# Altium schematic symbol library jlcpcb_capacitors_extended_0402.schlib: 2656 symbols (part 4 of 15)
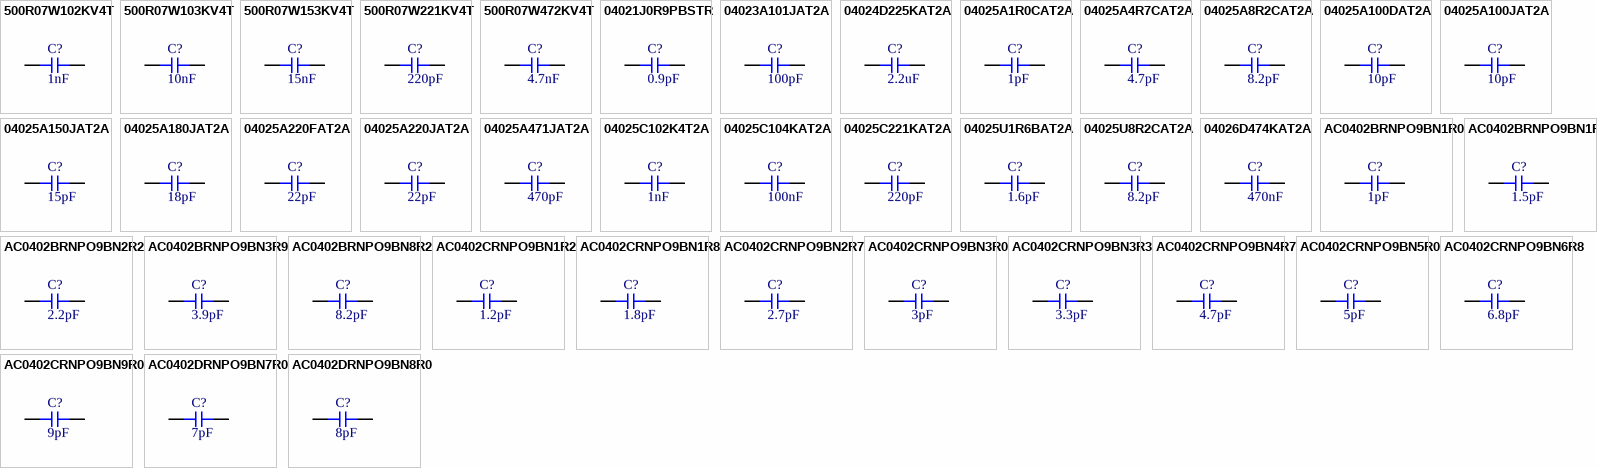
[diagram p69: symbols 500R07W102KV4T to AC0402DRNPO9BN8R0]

## 04026D474KAT2A
designator C?  Capacitance: 470nF  (hidden comment: *)
Capacitor, Ceramic (MLCC), 470nF, ±10%, 6.3V, X5R, ±10%, SMD 0402; Manufacturer: AVX; Manufacturer Part Number: 04026D474KAT2A
footprint CAP-0402 (0402 (1005M) Capacitor)
pins: 1, 2

## AC0402BRNPO9BN1R0
designator C?  Capacitance: 1pF  (hidden comment: *)
Capacitor, Ceramic (MLCC), 1pF, ±0.1pF, 50V, NP0, ±0.1pF, SMD 0402; Manufacturer: YAGEO; Manufacturer Part Number: AC0402BRNPO9BN1R0
footprint CAP-0402 (0402 (1005M) Capacitor)
pins: 1, 2

## AC0402BRNPO9BN1R5
designator C?  Capacitance: 1.5pF  (hidden comment: *)
Capacitor, Ceramic (MLCC), 1.5pF, ±0.1pF, 50V, NP0, ±0.1pF, SMD 0402; Manufacturer: YAGEO; Manufacturer Part Number: AC0402BRNPO9BN1R5
footprint CAP-0402 (0402 (1005M) Capacitor)
pins: 1, 2

## AC0402BRNPO9BN2R2
designator C?  Capacitance: 2.2pF  (hidden comment: *)
Capacitor, Ceramic (MLCC), 2.2pF, ±0.1pF, 50V, NP0, ±0.1pF, SMD 0402; Manufacturer: YAGEO; Manufacturer Part Number: AC0402BRNPO9BN2R2
footprint CAP-0402 (0402 (1005M) Capacitor)
pins: 1, 2

## AC0402BRNPO9BN3R9
designator C?  Capacitance: 3.9pF  (hidden comment: *)
Capacitor, Ceramic (MLCC), 3.9pF, ±0.1pF, 50V, NP0, ±0.1pF, SMD 0402; Manufacturer: YAGEO; Manufacturer Part Number: AC0402BRNPO9BN3R9
footprint CAP-0402 (0402 (1005M) Capacitor)
pins: 1, 2

## AC0402BRNPO9BN8R2
designator C?  Capacitance: 8.2pF  (hidden comment: *)
Capacitor, Ceramic (MLCC), 8.2pF, ±0.1pF, 50V, NP0, ±0.1pF, SMD 0402; Manufacturer: YAGEO; Manufacturer Part Number: AC0402BRNPO9BN8R2
footprint CAP-0402 (0402 (1005M) Capacitor)
pins: 1, 2

## AC0402CRNPO9BN1R2
designator C?  Capacitance: 1.2pF  (hidden comment: *)
Capacitor, Ceramic (MLCC), 1.2pF, ±0.25pF, 50V, NP0, ±0.25pF, SMD 0402; Manufacturer: YAGEO; Manufacturer Part Number: AC0402CRNPO9BN1R2
footprint CAP-0402 (0402 (1005M) Capacitor)
pins: 1, 2

## AC0402CRNPO9BN1R8
designator C?  Capacitance: 1.8pF  (hidden comment: *)
Capacitor, Ceramic (MLCC), 1.8pF, ±0.25pF, 50V, NP0, ±0.25pF, SMD 0402; Manufacturer: YAGEO; Manufacturer Part Number: AC0402CRNPO9BN1R8
footprint CAP-0402 (0402 (1005M) Capacitor)
pins: 1, 2

## AC0402CRNPO9BN2R7
designator C?  Capacitance: 2.7pF  (hidden comment: *)
Capacitor, Ceramic (MLCC), 2.7pF, ±0.25pF, 50V, NP0, ±0.25pF, SMD 0402; Manufacturer: YAGEO; Manufacturer Part Number: AC0402CRNPO9BN2R7
footprint CAP-0402 (0402 (1005M) Capacitor)
pins: 1, 2

## AC0402CRNPO9BN3R0
designator C?  Capacitance: 3pF  (hidden comment: *)
Capacitor, Ceramic (MLCC), 3pF, ±0.25pF, 50V, NP0, ±0.25pF, SMD 0402; Manufacturer: YAGEO; Manufacturer Part Number: AC0402CRNPO9BN3R0
footprint CAP-0402 (0402 (1005M) Capacitor)
pins: 1, 2

## AC0402CRNPO9BN3R3
designator C?  Capacitance: 3.3pF  (hidden comment: *)
Capacitor, Ceramic (MLCC), 3.3pF, ±0.25pF, 50V, NP0, ±0.25pF, SMD 0402; Manufacturer: YAGEO; Manufacturer Part Number: AC0402CRNPO9BN3R3
footprint CAP-0402 (0402 (1005M) Capacitor)
pins: 1, 2

## AC0402CRNPO9BN4R7
designator C?  Capacitance: 4.7pF  (hidden comment: *)
Capacitor, Ceramic (MLCC), 4.7pF, ±0.25pF, 50V, NP0, ±0.25pF, SMD 0402; Manufacturer: YAGEO; Manufacturer Part Number: AC0402CRNPO9BN4R7
footprint CAP-0402 (0402 (1005M) Capacitor)
pins: 1, 2

## AC0402CRNPO9BN5R0
designator C?  Capacitance: 5pF  (hidden comment: *)
Capacitor, Ceramic (MLCC), 5pF, ±0.25pF, 50V, NP0, ±0.25pF, SMD 0402; Manufacturer: YAGEO; Manufacturer Part Number: AC0402CRNPO9BN5R0
footprint CAP-0402 (0402 (1005M) Capacitor)
pins: 1, 2

## AC0402CRNPO9BN6R8
designator C?  Capacitance: 6.8pF  (hidden comment: *)
Capacitor, Ceramic (MLCC), 6.8pF, ±0.25pF, 50V, NP0, ±0.25pF, SMD 0402; Manufacturer: YAGEO; Manufacturer Part Number: AC0402CRNPO9BN6R8
footprint CAP-0402 (0402 (1005M) Capacitor)
pins: 1, 2

## AC0402CRNPO9BN9R0
designator C?  Capacitance: 9pF  (hidden comment: *)
Capacitor, Ceramic (MLCC), 9pF, ±0.25pF, 50V, NP0, ±0.25pF, SMD 0402; Manufacturer: YAGEO; Manufacturer Part Number: AC0402CRNPO9BN9R0
footprint CAP-0402 (0402 (1005M) Capacitor)
pins: 1, 2

## AC0402DRNPO9BN7R0
designator C?  Capacitance: 7pF  (hidden comment: *)
Capacitor, Ceramic (MLCC), 7pF, ±0.5pF, 50V, NP0, ±0.5pF, SMD 0402; Manufacturer: YAGEO; Manufacturer Part Number: AC0402DRNPO9BN7R0
footprint CAP-0402 (0402 (1005M) Capacitor)
pins: 1, 2

## AC0402DRNPO9BN8R0
designator C?  Capacitance: 8pF  (hidden comment: *)
Capacitor, Ceramic (MLCC), 8pF, ±0.5pF, 50V, NP0, ±0.5pF, SMD 0402; Manufacturer: YAGEO; Manufacturer Part Number: AC0402DRNPO9BN8R0
footprint CAP-0402 (0402 (1005M) Capacitor)
pins: 1, 2

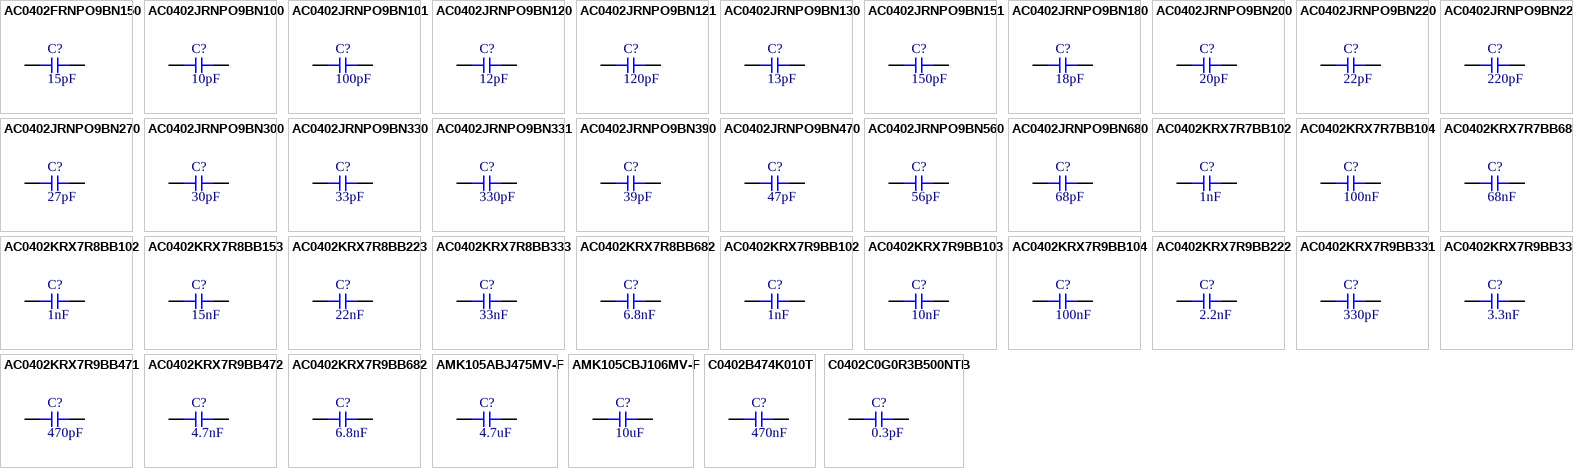
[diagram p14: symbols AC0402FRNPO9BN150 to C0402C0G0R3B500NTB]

## AC0402FRNPO9BN150
designator C?  Capacitance: 15pF  (hidden comment: *)
Capacitor, Ceramic (MLCC), 15pF, ±1%, 50V, NP0, ±1%, SMD 0402; Manufacturer: YAGEO; Manufacturer Part Number: AC0402FRNPO9BN150
footprint CAP-0402 (0402 (1005M) Capacitor)
pins: 1, 2

## AC0402JRNPO9BN100
designator C?  Capacitance: 10pF  (hidden comment: *)
Capacitor, Ceramic (MLCC), 10pF, ±5%, 50V, NP0, ±5%, SMD 0402; Manufacturer: YAGEO; Manufacturer Part Number: AC0402JRNPO9BN100
footprint CAP-0402 (0402 (1005M) Capacitor)
pins: 1, 2

## AC0402JRNPO9BN101
designator C?  Capacitance: 100pF  (hidden comment: *)
Capacitor, Ceramic (MLCC), 100pF, ±5%, 50V, NP0, ±5%, SMD 0402; Manufacturer: YAGEO; Manufacturer Part Number: AC0402JRNPO9BN101
footprint CAP-0402 (0402 (1005M) Capacitor)
pins: 1, 2

## AC0402JRNPO9BN120
designator C?  Capacitance: 12pF  (hidden comment: *)
Capacitor, Ceramic (MLCC), 12pF, ±5%, 50V, NP0, ±5%, SMD 0402; Manufacturer: YAGEO; Manufacturer Part Number: AC0402JRNPO9BN120
footprint CAP-0402 (0402 (1005M) Capacitor)
pins: 1, 2

## AC0402JRNPO9BN121
designator C?  Capacitance: 120pF  (hidden comment: *)
Capacitor, Ceramic (MLCC), 120pF, ±5%, 50V, NP0, ±5%, SMD 0402; Manufacturer: YAGEO; Manufacturer Part Number: AC0402JRNPO9BN121
footprint CAP-0402 (0402 (1005M) Capacitor)
pins: 1, 2

## AC0402JRNPO9BN130
designator C?  Capacitance: 13pF  (hidden comment: *)
Capacitor, Ceramic (MLCC), 13pF, ±5%, 50V, NP0, ±5%, SMD 0402; Manufacturer: YAGEO; Manufacturer Part Number: AC0402JRNPO9BN130
footprint CAP-0402 (0402 (1005M) Capacitor)
pins: 1, 2

## AC0402JRNPO9BN151
designator C?  Capacitance: 150pF  (hidden comment: *)
Capacitor, Ceramic (MLCC), 150pF, ±5%, 50V, NP0, ±5%, SMD 0402; Manufacturer: YAGEO; Manufacturer Part Number: AC0402JRNPO9BN151
footprint CAP-0402 (0402 (1005M) Capacitor)
pins: 1, 2

## AC0402JRNPO9BN180
designator C?  Capacitance: 18pF  (hidden comment: *)
Capacitor, Ceramic (MLCC), 18pF, ±5%, 50V, NP0, ±5%, SMD 0402; Manufacturer: YAGEO; Manufacturer Part Number: AC0402JRNPO9BN180
footprint CAP-0402 (0402 (1005M) Capacitor)
pins: 1, 2

## AC0402JRNPO9BN200
designator C?  Capacitance: 20pF  (hidden comment: *)
Capacitor, Ceramic (MLCC), 20pF, ±5%, 50V, NP0, ±5%, SMD 0402; Manufacturer: YAGEO; Manufacturer Part Number: AC0402JRNPO9BN200
footprint CAP-0402 (0402 (1005M) Capacitor)
pins: 1, 2

## AC0402JRNPO9BN220
designator C?  Capacitance: 22pF  (hidden comment: *)
Capacitor, Ceramic (MLCC), 22pF, ±5%, 50V, NP0, ±5%, SMD 0402; Manufacturer: YAGEO; Manufacturer Part Number: AC0402JRNPO9BN220
footprint CAP-0402 (0402 (1005M) Capacitor)
pins: 1, 2

## AC0402JRNPO9BN221
designator C?  Capacitance: 220pF  (hidden comment: *)
Capacitor, Ceramic (MLCC), 220pF, ±5%, 50V, NP0, ±5%, SMD 0402; Manufacturer: YAGEO; Manufacturer Part Number: AC0402JRNPO9BN221
footprint CAP-0402 (0402 (1005M) Capacitor)
pins: 1, 2

## AC0402JRNPO9BN270
designator C?  Capacitance: 27pF  (hidden comment: *)
Capacitor, Ceramic (MLCC), 27pF, ±5%, 50V, NP0, ±5%, SMD 0402; Manufacturer: YAGEO; Manufacturer Part Number: AC0402JRNPO9BN270
footprint CAP-0402 (0402 (1005M) Capacitor)
pins: 1, 2

## AC0402JRNPO9BN300
designator C?  Capacitance: 30pF  (hidden comment: *)
Capacitor, Ceramic (MLCC), 30pF, ±5%, 50V, NP0, ±5%, SMD 0402; Manufacturer: YAGEO; Manufacturer Part Number: AC0402JRNPO9BN300
footprint CAP-0402 (0402 (1005M) Capacitor)
pins: 1, 2

## AC0402JRNPO9BN330
designator C?  Capacitance: 33pF  (hidden comment: *)
Capacitor, Ceramic (MLCC), 33pF, ±5%, 50V, NP0, ±5%, SMD 0402; Manufacturer: YAGEO; Manufacturer Part Number: AC0402JRNPO9BN330
footprint CAP-0402 (0402 (1005M) Capacitor)
pins: 1, 2

## AC0402JRNPO9BN331
designator C?  Capacitance: 330pF  (hidden comment: *)
Capacitor, Ceramic (MLCC), 330pF, ±5%, 50V, NP0, ±5%, SMD 0402; Manufacturer: YAGEO; Manufacturer Part Number: AC0402JRNPO9BN331
footprint CAP-0402 (0402 (1005M) Capacitor)
pins: 1, 2

## AC0402JRNPO9BN390
designator C?  Capacitance: 39pF  (hidden comment: *)
Capacitor, Ceramic (MLCC), 39pF, ±5%, 50V, NP0, ±5%, SMD 0402; Manufacturer: YAGEO; Manufacturer Part Number: AC0402JRNPO9BN390
footprint CAP-0402 (0402 (1005M) Capacitor)
pins: 1, 2

## AC0402JRNPO9BN470
designator C?  Capacitance: 47pF  (hidden comment: *)
Capacitor, Ceramic (MLCC), 47pF, ±5%, 50V, NP0, ±5%, SMD 0402; Manufacturer: YAGEO; Manufacturer Part Number: AC0402JRNPO9BN470
footprint CAP-0402 (0402 (1005M) Capacitor)
pins: 1, 2

## AC0402JRNPO9BN560
designator C?  Capacitance: 56pF  (hidden comment: *)
Capacitor, Ceramic (MLCC), 56pF, ±5%, 50V, NP0, ±5%, SMD 0402; Manufacturer: YAGEO; Manufacturer Part Number: AC0402JRNPO9BN560
footprint CAP-0402 (0402 (1005M) Capacitor)
pins: 1, 2

## AC0402JRNPO9BN680
designator C?  Capacitance: 68pF  (hidden comment: *)
Capacitor, Ceramic (MLCC), 68pF, ±5%, 50V, NP0, ±5%, SMD 0402; Manufacturer: YAGEO; Manufacturer Part Number: AC0402JRNPO9BN680
footprint CAP-0402 (0402 (1005M) Capacitor)
pins: 1, 2

## AC0402KRX7R7BB102
designator C?  Capacitance: 1nF  (hidden comment: *)
Capacitor, Ceramic (MLCC), 1nF, ±10%, 16V, X7R, ±10%, SMD 0402; Manufacturer: YAGEO; Manufacturer Part Number: AC0402KRX7R7BB102
footprint CAP-0402 (0402 (1005M) Capacitor)
pins: 1, 2

## AC0402KRX7R7BB104
designator C?  Capacitance: 100nF  (hidden comment: *)
Capacitor, Ceramic (MLCC), 100nF, ±10%, 16V, X7R, ±10%, SMD 0402; Manufacturer: YAGEO; Manufacturer Part Number: AC0402KRX7R7BB104
footprint CAP-0402 (0402 (1005M) Capacitor)
pins: 1, 2

## AC0402KRX7R7BB683
designator C?  Capacitance: 68nF  (hidden comment: *)
Capacitor, Ceramic (MLCC), 68nF, ±10%, 16V, X7R, ±10%, SMD 0402; Manufacturer: YAGEO; Manufacturer Part Number: AC0402KRX7R7BB683
footprint CAP-0402 (0402 (1005M) Capacitor)
pins: 1, 2

## AC0402KRX7R8BB102
designator C?  Capacitance: 1nF  (hidden comment: *)
Capacitor, Ceramic (MLCC), 1nF, ±10%, 25V, X7R, ±10%, SMD 0402; Manufacturer: YAGEO; Manufacturer Part Number: AC0402KRX7R8BB102
footprint CAP-0402 (0402 (1005M) Capacitor)
pins: 1, 2

## AC0402KRX7R8BB153
designator C?  Capacitance: 15nF  (hidden comment: *)
Capacitor, Ceramic (MLCC), 15nF, ±10%, 25V, X7R, ±10%, SMD 0402; Manufacturer: YAGEO; Manufacturer Part Number: AC0402KRX7R8BB153
footprint CAP-0402 (0402 (1005M) Capacitor)
pins: 1, 2

## AC0402KRX7R8BB223
designator C?  Capacitance: 22nF  (hidden comment: *)
Capacitor, Ceramic (MLCC), 22nF, ±10%, 25V, X7R, ±10%, SMD 0402; Manufacturer: YAGEO; Manufacturer Part Number: AC0402KRX7R8BB223
footprint CAP-0402 (0402 (1005M) Capacitor)
pins: 1, 2

## AC0402KRX7R8BB333
designator C?  Capacitance: 33nF  (hidden comment: *)
Capacitor, Ceramic (MLCC), 33nF, ±10%, 25V, X7R, ±10%, SMD 0402; Manufacturer: YAGEO; Manufacturer Part Number: AC0402KRX7R8BB333
footprint CAP-0402 (0402 (1005M) Capacitor)
pins: 1, 2

## AC0402KRX7R8BB682
designator C?  Capacitance: 6.8nF  (hidden comment: *)
Capacitor, Ceramic (MLCC), 6.8nF, ±10%, 25V, X7R, ±10%, SMD 0402; Manufacturer: YAGEO; Manufacturer Part Number: AC0402KRX7R8BB682
footprint CAP-0402 (0402 (1005M) Capacitor)
pins: 1, 2

## AC0402KRX7R9BB102
designator C?  Capacitance: 1nF  (hidden comment: *)
Capacitor, Ceramic (MLCC), 1nF, ±10%, 50V, X7R, ±10%, SMD 0402; Manufacturer: YAGEO; Manufacturer Part Number: AC0402KRX7R9BB102
footprint CAP-0402 (0402 (1005M) Capacitor)
pins: 1, 2

## AC0402KRX7R9BB103
designator C?  Capacitance: 10nF  (hidden comment: *)
Capacitor, Ceramic (MLCC), 10nF, ±10%, 50V, X7R, ±10%, SMD 0402; Manufacturer: YAGEO; Manufacturer Part Number: AC0402KRX7R9BB103
footprint CAP-0402 (0402 (1005M) Capacitor)
pins: 1, 2

## AC0402KRX7R9BB104
designator C?  Capacitance: 100nF  (hidden comment: *)
Capacitor, Ceramic (MLCC), 100nF, ±10%, 50V, X7R, ±10%, SMD 0402; Manufacturer: YAGEO; Manufacturer Part Number: AC0402KRX7R9BB104
footprint CAP-0402 (0402 (1005M) Capacitor)
pins: 1, 2

## AC0402KRX7R9BB222
designator C?  Capacitance: 2.2nF  (hidden comment: *)
Capacitor, Ceramic (MLCC), 2.2nF, ±10%, 50V, X7R, ±10%, SMD 0402; Manufacturer: YAGEO; Manufacturer Part Number: AC0402KRX7R9BB222
footprint CAP-0402 (0402 (1005M) Capacitor)
pins: 1, 2

## AC0402KRX7R9BB331
designator C?  Capacitance: 330pF  (hidden comment: *)
Capacitor, Ceramic (MLCC), 330pF, ±10%, 50V, X7R, ±10%, SMD 0402; Manufacturer: YAGEO; Manufacturer Part Number: AC0402KRX7R9BB331
footprint CAP-0402 (0402 (1005M) Capacitor)
pins: 1, 2

## AC0402KRX7R9BB332
designator C?  Capacitance: 3.3nF  (hidden comment: *)
Capacitor, Ceramic (MLCC), 3.3nF, ±10%, 50V, X7R, ±10%, SMD 0402; Manufacturer: YAGEO; Manufacturer Part Number: AC0402KRX7R9BB332
footprint CAP-0402 (0402 (1005M) Capacitor)
pins: 1, 2

## AC0402KRX7R9BB471
designator C?  Capacitance: 470pF  (hidden comment: *)
Capacitor, Ceramic (MLCC), 470pF, ±10%, 50V, X7R, ±10%, SMD 0402; Manufacturer: YAGEO; Manufacturer Part Number: AC0402KRX7R9BB471
footprint CAP-0402 (0402 (1005M) Capacitor)
pins: 1, 2

## AC0402KRX7R9BB472
designator C?  Capacitance: 4.7nF  (hidden comment: *)
Capacitor, Ceramic (MLCC), 4.7nF, ±10%, 50V, X7R, ±10%, SMD 0402; Manufacturer: YAGEO; Manufacturer Part Number: AC0402KRX7R9BB472
footprint CAP-0402 (0402 (1005M) Capacitor)
pins: 1, 2

## AC0402KRX7R9BB682
designator C?  Capacitance: 6.8nF  (hidden comment: *)
Capacitor, Ceramic (MLCC), 6.8nF, ±10%, 50V, X7R, ±10%, SMD 0402; Manufacturer: YAGEO; Manufacturer Part Number: AC0402KRX7R9BB682
footprint CAP-0402 (0402 (1005M) Capacitor)
pins: 1, 2

## AMK105ABJ475MV-F
designator C?  Capacitance: 4.7uF  (hidden comment: *)
Capacitor, Ceramic (MLCC), 4.7uF, ±20%, 4V, X5R, ±20%, SMD 0402; Manufacturer: Taiyo Yuden; Manufacturer Part Number: AMK105ABJ475MV-F
footprint CAP-0402 (0402 (1005M) Capacitor)
pins: 1, 2

## AMK105CBJ106MV-F
designator C?  Capacitance: 10uF  (hidden comment: *)
Capacitor, Ceramic (MLCC), 10uF, ±20%, 4V, X5R, ±20%, SMD 0402; Manufacturer: Taiyo Yuden; Manufacturer Part Number: AMK105CBJ106MV-F
footprint CAP-0402 (0402 (1005M) Capacitor)
pins: 1, 2

## C0402B474K010T
designator C?  Capacitance: 470nF  (hidden comment: *)
Capacitor, Ceramic (MLCC), 470nF, ±10%, 10V, X5R, ±10%, SMD 0402; Manufacturer: IHHEC(HOLY STONE ENTERPRISE CO., LTD); Manufacturer Part Number: C0402B474K010T
footprint CAP-0402 (0402 (1005M) Capacitor)
pins: 1, 2

## C0402C0G0R3B500NTB
designator C?  Capacitance: 0.3pF  (hidden comment: *)
Capacitor, Ceramic (MLCC), 0.3pF, ±0.1pF, 50V, C0G, ±0.1pF, SMD 0402; Manufacturer: EYANG(Shenzhen Eyang Tech Development); Manufacturer Part Number: C0402C0G0R3B500NTB
footprint CAP-0402 (0402 (1005M) Capacitor)
pins: 1, 2

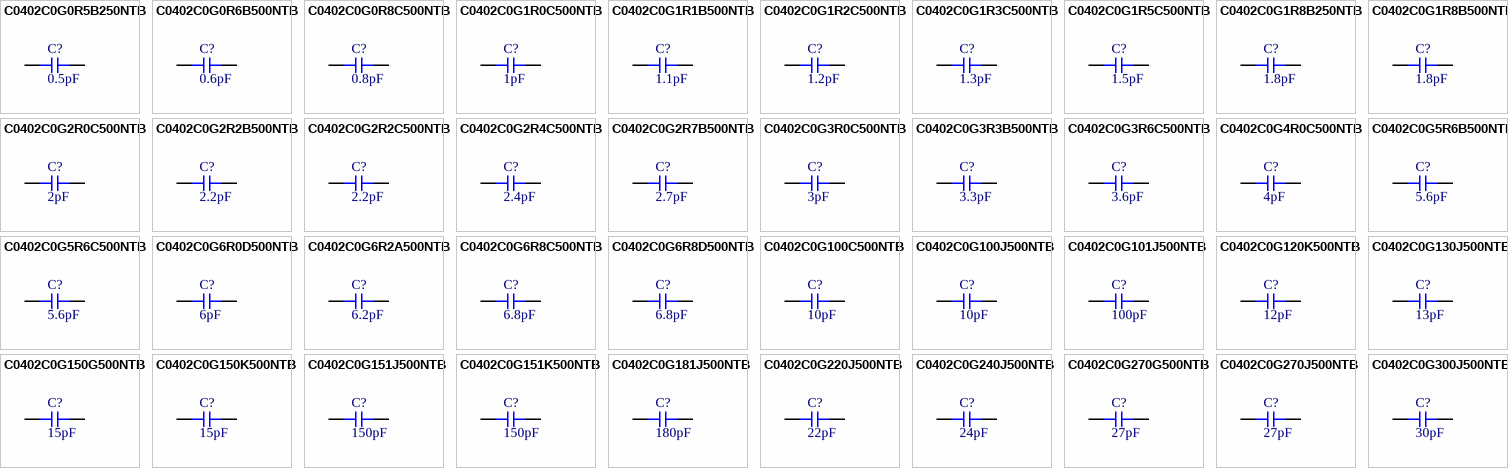
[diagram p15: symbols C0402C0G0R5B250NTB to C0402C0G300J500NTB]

## C0402C0G0R5B250NTB
designator C?  Capacitance: 0.5pF  (hidden comment: *)
Capacitor, Ceramic (MLCC), 0.5pF, ±0.1pF, 25V, C0G, ±0.1pF, SMD 0402; Manufacturer: EYANG(Shenzhen Eyang Tech Development); Manufacturer Part Number: C0402C0G0R5B250NTB
footprint CAP-0402 (0402 (1005M) Capacitor)
pins: 1, 2

## C0402C0G0R6B500NTB
designator C?  Capacitance: 0.6pF  (hidden comment: *)
Capacitor, Ceramic (MLCC), 0.6pF, ±0.1pF, 50V, C0G, ±0.1pF, SMD 0402; Manufacturer: EYANG(Shenzhen Eyang Tech Development); Manufacturer Part Number: C0402C0G0R6B500NTB
footprint CAP-0402 (0402 (1005M) Capacitor)
pins: 1, 2

## C0402C0G0R8C500NTB
designator C?  Capacitance: 0.8pF  (hidden comment: *)
Capacitor, Ceramic (MLCC), 0.8pF, ±0.25pF, 50V, C0G, ±0.25pF, SMD 0402; Manufacturer: EYANG(Shenzhen Eyang Tech Development); Manufacturer Part Number: C0402C0G0R8C500NTB
footprint CAP-0402 (0402 (1005M) Capacitor)
pins: 1, 2

## C0402C0G1R0C500NTB
designator C?  Capacitance: 1pF  (hidden comment: *)
Capacitor, Ceramic (MLCC), 1pF, ±0.25pF, 50V, C0G, ±0.25pF, SMD 0402; Manufacturer: EYANG(Shenzhen Eyang Tech Development); Manufacturer Part Number: C0402C0G1R0C500NTB
footprint CAP-0402 (0402 (1005M) Capacitor)
pins: 1, 2

## C0402C0G1R1B500NTB
designator C?  Capacitance: 1.1pF  (hidden comment: *)
Capacitor, Ceramic (MLCC), 1.1pF, ±0.1pF, 50V, C0G, ±0.1pF, SMD 0402; Manufacturer: EYANG(Shenzhen Eyang Tech Development); Manufacturer Part Number: C0402C0G1R1B500NTB
footprint CAP-0402 (0402 (1005M) Capacitor)
pins: 1, 2

## C0402C0G1R2C500NTB
designator C?  Capacitance: 1.2pF  (hidden comment: *)
Capacitor, Ceramic (MLCC), 1.2pF, ±0.25pF, 50V, C0G, ±0.25pF, SMD 0402; Manufacturer: EYANG(Shenzhen Eyang Tech Development); Manufacturer Part Number: C0402C0G1R2C500NTB
footprint CAP-0402 (0402 (1005M) Capacitor)
pins: 1, 2

## C0402C0G1R3C500NTB
designator C?  Capacitance: 1.3pF  (hidden comment: *)
Capacitor, Ceramic (MLCC), 1.3pF, ±0.25pF, 50V, C0G, ±0.25pF, SMD 0402; Manufacturer: EYANG(Shenzhen Eyang Tech Development); Manufacturer Part Number: C0402C0G1R3C500NTB
footprint CAP-0402 (0402 (1005M) Capacitor)
pins: 1, 2

## C0402C0G1R5C500NTB
designator C?  Capacitance: 1.5pF  (hidden comment: *)
Capacitor, Ceramic (MLCC), 1.5pF, ±0.25pF, 50V, C0G, ±0.25pF, SMD 0402; Manufacturer: EYANG(Shenzhen Eyang Tech Development); Manufacturer Part Number: C0402C0G1R5C500NTB
footprint CAP-0402 (0402 (1005M) Capacitor)
pins: 1, 2

## C0402C0G1R8B250NTB
designator C?  Capacitance: 1.8pF  (hidden comment: *)
Capacitor, Ceramic (MLCC), 1.8pF, ±0.1pF, 25V, C0G, ±0.1pF, SMD 0402; Manufacturer: EYANG(Shenzhen Eyang Tech Development); Manufacturer Part Number: C0402C0G1R8B250NTB
footprint CAP-0402 (0402 (1005M) Capacitor)
pins: 1, 2

## C0402C0G1R8B500NTB
designator C?  Capacitance: 1.8pF  (hidden comment: *)
Capacitor, Ceramic (MLCC), 1.8pF, ±0.1pF, 50V, C0G, ±0.1pF, SMD 0402; Manufacturer: EYANG(Shenzhen Eyang Tech Development); Manufacturer Part Number: C0402C0G1R8B500NTB
footprint CAP-0402 (0402 (1005M) Capacitor)
pins: 1, 2

## C0402C0G2R0C500NTB
designator C?  Capacitance: 2pF  (hidden comment: *)
Capacitor, Ceramic (MLCC), 2pF, ±0.25pF, 50V, C0G, ±0.25pF, SMD 0402; Manufacturer: EYANG(Shenzhen Eyang Tech Development); Manufacturer Part Number: C0402C0G2R0C500NTB
footprint CAP-0402 (0402 (1005M) Capacitor)
pins: 1, 2

## C0402C0G2R2B500NTB
designator C?  Capacitance: 2.2pF  (hidden comment: *)
Capacitor, Ceramic (MLCC), 2.2pF, ±0.1pF, 50V, C0G, ±0.1pF, SMD 0402; Manufacturer: EYANG(Shenzhen Eyang Tech Development); Manufacturer Part Number: C0402C0G2R2B500NTB
footprint CAP-0402 (0402 (1005M) Capacitor)
pins: 1, 2

## C0402C0G2R2C500NTB
designator C?  Capacitance: 2.2pF  (hidden comment: *)
Capacitor, Ceramic (MLCC), 2.2pF, ±0.25pF, 50V, C0G, ±0.25pF, SMD 0402; Manufacturer: EYANG(Shenzhen Eyang Tech Development); Manufacturer Part Number: C0402C0G2R2C500NTB
footprint CAP-0402 (0402 (1005M) Capacitor)
pins: 1, 2

## C0402C0G2R4C500NTB
designator C?  Capacitance: 2.4pF  (hidden comment: *)
Capacitor, Ceramic (MLCC), 2.4pF, ±0.25pF, 50V, C0G, ±0.25pF, SMD 0402; Manufacturer: EYANG(Shenzhen Eyang Tech Development); Manufacturer Part Number: C0402C0G2R4C500NTB
footprint CAP-0402 (0402 (1005M) Capacitor)
pins: 1, 2

## C0402C0G2R7B500NTB
designator C?  Capacitance: 2.7pF  (hidden comment: *)
Capacitor, Ceramic (MLCC), 2.7pF, ±0.1pF, 50V, C0G, ±0.1pF, SMD 0402; Manufacturer: EYANG(Shenzhen Eyang Tech Development); Manufacturer Part Number: C0402C0G2R7B500NTB
footprint CAP-0402 (0402 (1005M) Capacitor)
pins: 1, 2

## C0402C0G3R0C500NTB
designator C?  Capacitance: 3pF  (hidden comment: *)
Capacitor, Ceramic (MLCC), 3pF, ±0.25pF, 50V, C0G, ±0.25pF, SMD 0402; Manufacturer: EYANG(Shenzhen Eyang Tech Development); Manufacturer Part Number: C0402C0G3R0C500NTB
footprint CAP-0402 (0402 (1005M) Capacitor)
pins: 1, 2

## C0402C0G3R3B500NTB
designator C?  Capacitance: 3.3pF  (hidden comment: *)
Capacitor, Ceramic (MLCC), 3.3pF, ±0.1pF, 50V, C0G, ±0.1pF, SMD 0402; Manufacturer: EYANG(Shenzhen Eyang Tech Development); Manufacturer Part Number: C0402C0G3R3B500NTB
footprint CAP-0402 (0402 (1005M) Capacitor)
pins: 1, 2

## C0402C0G3R6C500NTB
designator C?  Capacitance: 3.6pF  (hidden comment: *)
Capacitor, Ceramic (MLCC), 3.6pF, ±0.25pF, 50V, C0G, ±0.25pF, SMD 0402; Manufacturer: EYANG(Shenzhen Eyang Tech Development); Manufacturer Part Number: C0402C0G3R6C500NTB
footprint CAP-0402 (0402 (1005M) Capacitor)
pins: 1, 2

## C0402C0G4R0C500NTB
designator C?  Capacitance: 4pF  (hidden comment: *)
Capacitor, Ceramic (MLCC), 4pF, ±0.25pF, 50V, C0G, ±0.25pF, SMD 0402; Manufacturer: EYANG(Shenzhen Eyang Tech Development); Manufacturer Part Number: C0402C0G4R0C500NTB
footprint CAP-0402 (0402 (1005M) Capacitor)
pins: 1, 2

## C0402C0G5R6B500NTB
designator C?  Capacitance: 5.6pF  (hidden comment: *)
Capacitor, Ceramic (MLCC), 5.6pF, ±0.1pF, 50V, C0G, ±0.1pF, SMD 0402; Manufacturer: EYANG(Shenzhen Eyang Tech Development); Manufacturer Part Number: C0402C0G5R6B500NTB
footprint CAP-0402 (0402 (1005M) Capacitor)
pins: 1, 2

## C0402C0G5R6C500NTB
designator C?  Capacitance: 5.6pF  (hidden comment: *)
Capacitor, Ceramic (MLCC), 5.6pF, ±0.25pF, 50V, C0G, ±0.25pF, SMD 0402; Manufacturer: EYANG(Shenzhen Eyang Tech Development); Manufacturer Part Number: C0402C0G5R6C500NTB
footprint CAP-0402 (0402 (1005M) Capacitor)
pins: 1, 2

## C0402C0G6R0D500NTB
designator C?  Capacitance: 6pF  (hidden comment: *)
Capacitor, Ceramic (MLCC), 6pF, ±0.5pF, 50V, C0G, ±0.5pF, SMD 0402; Manufacturer: EYANG(Shenzhen Eyang Tech Development); Manufacturer Part Number: C0402C0G6R0D500NTB
footprint CAP-0402 (0402 (1005M) Capacitor)
pins: 1, 2

## C0402C0G6R2A500NTB
designator C?  Capacitance: 6.2pF  (hidden comment: *)
Capacitor, Ceramic (MLCC), 6.2pF, ±0.05pF, 50V, C0G, ±0.05pF, SMD 0402; Manufacturer: EYANG(Shenzhen Eyang Tech Development); Manufacturer Part Number: C0402C0G6R2A500NTB
footprint CAP-0402 (0402 (1005M) Capacitor)
pins: 1, 2

## C0402C0G6R8C500NTB
designator C?  Capacitance: 6.8pF  (hidden comment: *)
Capacitor, Ceramic (MLCC), 6.8pF, ±0.25pF, 50V, C0G, ±0.25pF, SMD 0402; Manufacturer: EYANG(Shenzhen Eyang Tech Development); Manufacturer Part Number: C0402C0G6R8C500NTB
footprint CAP-0402 (0402 (1005M) Capacitor)
pins: 1, 2

## C0402C0G6R8D500NTB
designator C?  Capacitance: 6.8pF  (hidden comment: *)
Capacitor, Ceramic (MLCC), 6.8pF, ±0.5pF, 50V, C0G, ±0.5pF, SMD 0402; Manufacturer: EYANG(Shenzhen Eyang Tech Development); Manufacturer Part Number: C0402C0G6R8D500NTB
footprint CAP-0402 (0402 (1005M) Capacitor)
pins: 1, 2

## C0402C0G100C500NTB
designator C?  Capacitance: 10pF  (hidden comment: *)
Capacitor, Ceramic (MLCC), 10pF, ±0.25pF, 50V, C0G, ±0.25pF, SMD 0402; Manufacturer: EYANG(Shenzhen Eyang Tech Development); Manufacturer Part Number: C0402C0G100C500NTB
footprint CAP-0402 (0402 (1005M) Capacitor)
pins: 1, 2

## C0402C0G100J500NTB
designator C?  Capacitance: 10pF  (hidden comment: *)
Capacitor, Ceramic (MLCC), 10pF, ±5%, 50V, C0G, ±5%, SMD 0402; Manufacturer: EYANG(Shenzhen Eyang Tech Development); Manufacturer Part Number: C0402C0G100J500NTB
footprint CAP-0402 (0402 (1005M) Capacitor)
pins: 1, 2

## C0402C0G101J500NTB
designator C?  Capacitance: 100pF  (hidden comment: *)
Capacitor, Ceramic (MLCC), 100pF, ±5%, 50V, C0G, ±5%, SMD 0402; Manufacturer: EYANG(Shenzhen Eyang Tech Development); Manufacturer Part Number: C0402C0G101J500NTB
footprint CAP-0402 (0402 (1005M) Capacitor)
pins: 1, 2

## C0402C0G120K500NTB
designator C?  Capacitance: 12pF  (hidden comment: *)
Capacitor, Ceramic (MLCC), 12pF, ±10%, 50V, C0G, ±10%, SMD 0402; Manufacturer: EYANG(Shenzhen Eyang Tech Development); Manufacturer Part Number: C0402C0G120K500NTB
footprint CAP-0402 (0402 (1005M) Capacitor)
pins: 1, 2

## C0402C0G130J500NTB
designator C?  Capacitance: 13pF  (hidden comment: *)
Capacitor, Ceramic (MLCC), 13pF, ±5%, 50V, C0G, ±5%, SMD 0402; Manufacturer: EYANG(Shenzhen Eyang Tech Development); Manufacturer Part Number: C0402C0G130J500NTB
footprint CAP-0402 (0402 (1005M) Capacitor)
pins: 1, 2

## C0402C0G150G500NTB
designator C?  Capacitance: 15pF  (hidden comment: *)
Capacitor, Ceramic (MLCC), 15pF, ±2%, 50V, C0G, ±2%, SMD 0402; Manufacturer: EYANG(Shenzhen Eyang Tech Development); Manufacturer Part Number: C0402C0G150G500NTB
footprint CAP-0402 (0402 (1005M) Capacitor)
pins: 1, 2

## C0402C0G150K500NTB
designator C?  Capacitance: 15pF  (hidden comment: *)
Capacitor, Ceramic (MLCC), 15pF, ±10%, 50V, C0G, ±10%, SMD 0402; Manufacturer: EYANG(Shenzhen Eyang Tech Development); Manufacturer Part Number: C0402C0G150K500NTB
footprint CAP-0402 (0402 (1005M) Capacitor)
pins: 1, 2

## C0402C0G151J500NTB
designator C?  Capacitance: 150pF  (hidden comment: *)
Capacitor, Ceramic (MLCC), 150pF, ±5%, 50V, C0G, ±5%, SMD 0402; Manufacturer: EYANG(Shenzhen Eyang Tech Development); Manufacturer Part Number: C0402C0G151J500NTB
footprint CAP-0402 (0402 (1005M) Capacitor)
pins: 1, 2

## C0402C0G151K500NTB
designator C?  Capacitance: 150pF  (hidden comment: *)
Capacitor, Ceramic (MLCC), 150pF, ±10%, 50V, C0G, ±10%, SMD 0402; Manufacturer: EYANG(Shenzhen Eyang Tech Development); Manufacturer Part Number: C0402C0G151K500NTB
footprint CAP-0402 (0402 (1005M) Capacitor)
pins: 1, 2

## C0402C0G181J500NTB
designator C?  Capacitance: 180pF  (hidden comment: *)
Capacitor, Ceramic (MLCC), 180pF, ±5%, 50V, C0G, ±5%, SMD 0402; Manufacturer: EYANG(Shenzhen Eyang Tech Development); Manufacturer Part Number: C0402C0G181J500NTB
footprint CAP-0402 (0402 (1005M) Capacitor)
pins: 1, 2

## C0402C0G220J500NTB
designator C?  Capacitance: 22pF  (hidden comment: *)
Capacitor, Ceramic (MLCC), 22pF, ±5%, 50V, C0G, ±5%, SMD 0402; Manufacturer: EYANG(Shenzhen Eyang Tech Development); Manufacturer Part Number: C0402C0G220J500NTB
footprint CAP-0402 (0402 (1005M) Capacitor)
pins: 1, 2

## C0402C0G240J500NTB
designator C?  Capacitance: 24pF  (hidden comment: *)
Capacitor, Ceramic (MLCC), 24pF, ±5%, 50V, C0G, ±5%, SMD 0402; Manufacturer: EYANG(Shenzhen Eyang Tech Development); Manufacturer Part Number: C0402C0G240J500NTB
footprint CAP-0402 (0402 (1005M) Capacitor)
pins: 1, 2

## C0402C0G270G500NTB
designator C?  Capacitance: 27pF  (hidden comment: *)
Capacitor, Ceramic (MLCC), 27pF, ±2%, 50V, C0G, ±2%, SMD 0402; Manufacturer: EYANG(Shenzhen Eyang Tech Development); Manufacturer Part Number: C0402C0G270G500NTB
footprint CAP-0402 (0402 (1005M) Capacitor)
pins: 1, 2

## C0402C0G270J500NTB
designator C?  Capacitance: 27pF  (hidden comment: *)
Capacitor, Ceramic (MLCC), 27pF, ±5%, 50V, C0G, ±5%, SMD 0402; Manufacturer: EYANG(Shenzhen Eyang Tech Development); Manufacturer Part Number: C0402C0G270J500NTB
footprint CAP-0402 (0402 (1005M) Capacitor)
pins: 1, 2

## C0402C0G300J500NTB
designator C?  Capacitance: 30pF  (hidden comment: *)
Capacitor, Ceramic (MLCC), 30pF, ±5%, 50V, C0G, ±5%, SMD 0402; Manufacturer: EYANG(Shenzhen Eyang Tech Development); Manufacturer Part Number: C0402C0G300J500NTB
footprint CAP-0402 (0402 (1005M) Capacitor)
pins: 1, 2

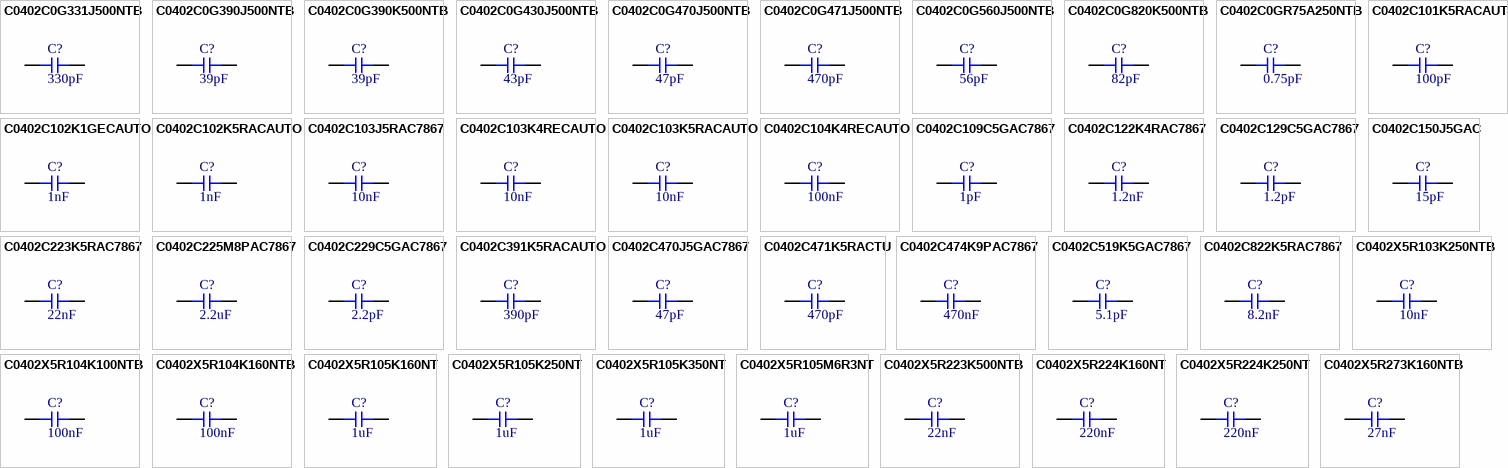
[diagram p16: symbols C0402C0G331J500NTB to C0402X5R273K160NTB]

## C0402C0G331J500NTB
designator C?  Capacitance: 330pF  (hidden comment: *)
Capacitor, Ceramic (MLCC), 330pF, ±5%, 50V, C0G, ±5%, SMD 0402; Manufacturer: EYANG(Shenzhen Eyang Tech Development); Manufacturer Part Number: C0402C0G331J500NTB
footprint CAP-0402 (0402 (1005M) Capacitor)
pins: 1, 2

## C0402C0G390J500NTB
designator C?  Capacitance: 39pF  (hidden comment: *)
Capacitor, Ceramic (MLCC), 39pF, ±5%, 50V, C0G, ±5%, SMD 0402; Manufacturer: EYANG(Shenzhen Eyang Tech Development); Manufacturer Part Number: C0402C0G390J500NTB
footprint CAP-0402 (0402 (1005M) Capacitor)
pins: 1, 2

## C0402C0G390K500NTB
designator C?  Capacitance: 39pF  (hidden comment: *)
Capacitor, Ceramic (MLCC), 39pF, ±10%, 50V, C0G, ±10%, SMD 0402; Manufacturer: EYANG(Shenzhen Eyang Tech Development); Manufacturer Part Number: C0402C0G390K500NTB
footprint CAP-0402 (0402 (1005M) Capacitor)
pins: 1, 2

## C0402C0G430J500NTB
designator C?  Capacitance: 43pF  (hidden comment: *)
Capacitor, Ceramic (MLCC), 43pF, ±5%, 50V, C0G, ±5%, SMD 0402; Manufacturer: EYANG(Shenzhen Eyang Tech Development); Manufacturer Part Number: C0402C0G430J500NTB
footprint CAP-0402 (0402 (1005M) Capacitor)
pins: 1, 2

## C0402C0G470J500NTB
designator C?  Capacitance: 47pF  (hidden comment: *)
Capacitor, Ceramic (MLCC), 47pF, ±5%, 50V, C0G, ±5%, SMD 0402; Manufacturer: EYANG(Shenzhen Eyang Tech Development); Manufacturer Part Number: C0402C0G470J500NTB
footprint CAP-0402 (0402 (1005M) Capacitor)
pins: 1, 2

## C0402C0G471J500NTB
designator C?  Capacitance: 470pF  (hidden comment: *)
Capacitor, Ceramic (MLCC), 470pF, ±5%, 50V, C0G, ±5%, SMD 0402; Manufacturer: EYANG(Shenzhen Eyang Tech Development); Manufacturer Part Number: C0402C0G471J500NTB
footprint CAP-0402 (0402 (1005M) Capacitor)
pins: 1, 2

## C0402C0G560J500NTB
designator C?  Capacitance: 56pF  (hidden comment: *)
Capacitor, Ceramic (MLCC), 56pF, ±5%, 50V, C0G, ±5%, SMD 0402; Manufacturer: EYANG(Shenzhen Eyang Tech Development); Manufacturer Part Number: C0402C0G560J500NTB
footprint CAP-0402 (0402 (1005M) Capacitor)
pins: 1, 2

## C0402C0G820K500NTB
designator C?  Capacitance: 82pF  (hidden comment: *)
Capacitor, Ceramic (MLCC), 82pF, ±10%, 50V, C0G, ±10%, SMD 0402; Manufacturer: EYANG(Shenzhen Eyang Tech Development); Manufacturer Part Number: C0402C0G820K500NTB
footprint CAP-0402 (0402 (1005M) Capacitor)
pins: 1, 2

## C0402C0GR75A250NTB
designator C?  Capacitance: 0.75pF  (hidden comment: *)
Capacitor, Ceramic (MLCC), 0.75pF, ±0.05pF, 25V, C0G, ±0.05pF, SMD 0402; Manufacturer: EYANG(Shenzhen Eyang Tech Development); Manufacturer Part Number: C0402C0GR75A250NTB
footprint CAP-0402 (0402 (1005M) Capacitor)
pins: 1, 2

## C0402C101K5RACAUTO
designator C?  Capacitance: 100pF  (hidden comment: *)
Capacitor, Ceramic (MLCC), 100pF, ±10%, 50V, X7R, ±10%, SMD 0402; Manufacturer: KEMET; Manufacturer Part Number: C0402C101K5RACAUTO
footprint CAP-0402 (0402 (1005M) Capacitor)
pins: 1, 2

## C0402C102K1GECAUTO
designator C?  Capacitance: 1nF  (hidden comment: *)
Capacitor, Ceramic (MLCC), 1nF, ±10%, 100V, C0G, ±10%, SMD 0402; Manufacturer: KEMET; Manufacturer Part Number: C0402C102K1GECAUTO
footprint CAP-0402 (0402 (1005M) Capacitor)
pins: 1, 2

## C0402C102K5RACAUTO
designator C?  Capacitance: 1nF  (hidden comment: *)
Capacitor, Ceramic (MLCC), 1nF, ±10%, 50V, X7R, ±10%, SMD 0402; Manufacturer: KEMET; Manufacturer Part Number: C0402C102K5RACAUTO
footprint CAP-0402 (0402 (1005M) Capacitor)
pins: 1, 2

## C0402C103J5RAC7867
designator C?  Capacitance: 10nF  (hidden comment: *)
Capacitor, Ceramic (MLCC), 10nF, ±5%, 50V, X7R, ±5%, SMD 0402; Manufacturer: KEMET; Manufacturer Part Number: C0402C103J5RAC7867
footprint CAP-0402 (0402 (1005M) Capacitor)
pins: 1, 2

## C0402C103K4RECAUTO
designator C?  Capacitance: 10nF  (hidden comment: *)
Capacitor, Ceramic (MLCC), 10nF, ±10%, 16V, X7R, ±10%, SMD 0402; Manufacturer: KEMET; Manufacturer Part Number: C0402C103K4RECAUTO
footprint CAP-0402 (0402 (1005M) Capacitor)
pins: 1, 2

## C0402C103K5RACAUTO
designator C?  Capacitance: 10nF  (hidden comment: *)
Capacitor, Ceramic (MLCC), 10nF, ±10%, 50V, X7R, ±10%, SMD 0402; Manufacturer: KEMET; Manufacturer Part Number: C0402C103K5RACAUTO
footprint CAP-0402 (0402 (1005M) Capacitor)
pins: 1, 2

## C0402C104K4RECAUTO
designator C?  Capacitance: 100nF  (hidden comment: *)
Capacitor, Ceramic (MLCC), 100nF, ±10%, 16V, X7R, ±10%, SMD 0402; Manufacturer: KEMET; Manufacturer Part Number: C0402C104K4RECAUTO
footprint CAP-0402 (0402 (1005M) Capacitor)
pins: 1, 2

## C0402C109C5GAC7867
designator C?  Capacitance: 1pF  (hidden comment: *)
Capacitor, Ceramic (MLCC), 1pF, ±0.25pF, 50V, C0G, ±0.25pF, SMD 0402; Manufacturer: KEMET; Manufacturer Part Number: C0402C109C5GAC7867
footprint CAP-0402 (0402 (1005M) Capacitor)
pins: 1, 2

## C0402C122K4RAC7867
designator C?  Capacitance: 1.2nF  (hidden comment: *)
Capacitor, Ceramic (MLCC), 1.2nF, ±10%, 16V, X7R, ±10%, SMD 0402; Manufacturer: KEMET; Manufacturer Part Number: C0402C122K4RAC7867
footprint CAP-0402 (0402 (1005M) Capacitor)
pins: 1, 2

## C0402C129C5GAC7867
designator C?  Capacitance: 1.2pF  (hidden comment: *)
Capacitor, Ceramic (MLCC), 1.2pF, ±0.25pF, 50V, C0G, ±0.25pF, SMD 0402; Manufacturer: KEMET; Manufacturer Part Number: C0402C129C5GAC7867
footprint CAP-0402 (0402 (1005M) Capacitor)
pins: 1, 2

## C0402C150J5GAC
designator C?  Capacitance: 15pF  (hidden comment: *)
Capacitor, Ceramic (MLCC), 15pF, ±5%, 50V, C0G, ±5%, SMD 0402; Manufacturer: KEMET; Manufacturer Part Number: C0402C150J5GAC
footprint CAP-0402 (0402 (1005M) Capacitor)
pins: 1, 2

## C0402C223K5RAC7867
designator C?  Capacitance: 22nF  (hidden comment: *)
Capacitor, Ceramic (MLCC), 22nF, ±10%, 50V, X7R, ±10%, SMD 0402; Manufacturer: KEMET; Manufacturer Part Number: C0402C223K5RAC7867
footprint CAP-0402 (0402 (1005M) Capacitor)
pins: 1, 2

## C0402C225M8PAC7867
designator C?  Capacitance: 2.2uF  (hidden comment: *)
Capacitor, Ceramic (MLCC), 2.2uF, ±20%, 10V, ±20%, SMD 0402; Manufacturer: KEMET; Manufacturer Part Number: C0402C225M8PAC7867
footprint CAP-0402 (0402 (1005M) Capacitor)
pins: 1, 2

## C0402C229C5GAC7867
designator C?  Capacitance: 2.2pF  (hidden comment: *)
Capacitor, Ceramic (MLCC), 2.2pF, ±0.25pF, 50V, C0G, ±0.25pF, SMD 0402; Manufacturer: KEMET; Manufacturer Part Number: C0402C229C5GAC7867
footprint CAP-0402 (0402 (1005M) Capacitor)
pins: 1, 2

## C0402C391K5RACAUTO
designator C?  Capacitance: 390pF  (hidden comment: *)
Capacitor, Ceramic (MLCC), 390pF, ±10%, 50V, X7R, ±10%, SMD 0402; Manufacturer: KEMET; Manufacturer Part Number: C0402C391K5RACAUTO
footprint CAP-0402 (0402 (1005M) Capacitor)
pins: 1, 2

## C0402C470J5GAC7867
designator C?  Capacitance: 47pF  (hidden comment: *)
Capacitor, Ceramic (MLCC), 47pF, ±5%, 50V, C0G, ±5%, SMD 0402; Manufacturer: KEMET; Manufacturer Part Number: C0402C470J5GAC7867
footprint CAP-0402 (0402 (1005M) Capacitor)
pins: 1, 2

## C0402C471K5RACTU
designator C?  Capacitance: 470pF  (hidden comment: *)
Capacitor, Ceramic (MLCC), 470pF, ±10%, 50V, X7R, ±10%, SMD 0402; Manufacturer: KEMET; Manufacturer Part Number: C0402C471K5RACTU
footprint CAP-0402 (0402 (1005M) Capacitor)
pins: 1, 2

## C0402C474K9PAC7867
designator C?  Capacitance: 470nF  (hidden comment: *)
Capacitor, Ceramic (MLCC), 470nF, ±10%, 6.3V, ±10%, SMD 0402; Manufacturer: KEMET; Manufacturer Part Number: C0402C474K9PAC7867
footprint CAP-0402 (0402 (1005M) Capacitor)
pins: 1, 2

## C0402C519K5GAC7867
designator C?  Capacitance: 5.1pF  (hidden comment: *)
Capacitor, Ceramic (MLCC), 5.1pF, ±10%, 50V, C0G, ±10%, SMD 0402; Manufacturer: KEMET; Manufacturer Part Number: C0402C519K5GAC7867
footprint CAP-0402 (0402 (1005M) Capacitor)
pins: 1, 2

## C0402C822K5RAC7867
designator C?  Capacitance: 8.2nF  (hidden comment: *)
Capacitor, Ceramic (MLCC), 8.2nF, ±10%, 50V, X7R, ±10%, SMD 0402; Manufacturer: KEMET; Manufacturer Part Number: C0402C822K5RAC7867
footprint CAP-0402 (0402 (1005M) Capacitor)
pins: 1, 2

## C0402X5R103K250NTB
designator C?  Capacitance: 10nF  (hidden comment: *)
Capacitor, Ceramic (MLCC), 10nF, ±10%, 25V, X5R, ±10%, SMD 0402; Manufacturer: EYANG(Shenzhen Eyang Tech Development); Manufacturer Part Number: C0402X5R103K250NTB
footprint CAP-0402 (0402 (1005M) Capacitor)
pins: 1, 2

## C0402X5R104K100NTB
designator C?  Capacitance: 100nF  (hidden comment: *)
Capacitor, Ceramic (MLCC), 100nF, ±10%, 10V, X5R, ±10%, SMD 0402; Manufacturer: EYANG(Shenzhen Eyang Tech Development); Manufacturer Part Number: C0402X5R104K100NTB
footprint CAP-0402 (0402 (1005M) Capacitor)
pins: 1, 2

## C0402X5R104K160NTB
designator C?  Capacitance: 100nF  (hidden comment: *)
Capacitor, Ceramic (MLCC), 100nF, ±10%, 16V, X5R, ±10%, SMD 0402; Manufacturer: EYANG(Shenzhen Eyang Tech Development); Manufacturer Part Number: C0402X5R104K160NTB
footprint CAP-0402 (0402 (1005M) Capacitor)
pins: 1, 2

## C0402X5R105K160NT
designator C?  Capacitance: 1uF  (hidden comment: *)
Capacitor, Ceramic (MLCC), 1uF, ±10%, 16V, ±10%, SMD 0402; Manufacturer: SANYEAR; Manufacturer Part Number: C0402X5R105K160NT
footprint CAP-0402 (0402 (1005M) Capacitor)
pins: 1, 2

## C0402X5R105K250NT
designator C?  Capacitance: 1uF  (hidden comment: *)
Capacitor, Ceramic (MLCC), 1uF, ±10%, 25V, X5R, ±10%, SMD 0402; Manufacturer: SANYEAR; Manufacturer Part Number: C0402X5R105K250NT
footprint CAP-0402 (0402 (1005M) Capacitor)
pins: 1, 2

## C0402X5R105K350NT
designator C?  Capacitance: 1uF  (hidden comment: *)
Capacitor, Ceramic (MLCC), 1uF, ±10%, 35V, ±10%, SMD 0402; Manufacturer: SANYEAR; Manufacturer Part Number: C0402X5R105K350NT
footprint CAP-0402 (0402 (1005M) Capacitor)
pins: 1, 2

## C0402X5R105M6R3NT
designator C?  Capacitance: 1uF  (hidden comment: *)
Capacitor, Ceramic (MLCC), 1uF, ±20%, 6.3V, X5R, ±20%, SMD 0402; Manufacturer: SANYEAR; Manufacturer Part Number: C0402X5R105M6R3NT
footprint CAP-0402 (0402 (1005M) Capacitor)
pins: 1, 2

## C0402X5R223K500NTB
designator C?  Capacitance: 22nF  (hidden comment: *)
Capacitor, Ceramic (MLCC), 22nF, ±10%, 50V, X5R, ±10%, SMD 0402; Manufacturer: EYANG(Shenzhen Eyang Tech Development); Manufacturer Part Number: C0402X5R223K500NTB
footprint CAP-0402 (0402 (1005M) Capacitor)
pins: 1, 2

## C0402X5R224K160NT
designator C?  Capacitance: 220nF  (hidden comment: *)
Capacitor, Ceramic (MLCC), 220nF, ±10%, 16V, X5R, ±10%, SMD 0402; Manufacturer: SANYEAR; Manufacturer Part Number: C0402X5R224K160NT
footprint CAP-0402 (0402 (1005M) Capacitor)
pins: 1, 2

## C0402X5R224K250NT
designator C?  Capacitance: 220nF  (hidden comment: *)
Capacitor, Ceramic (MLCC), 220nF, ±10%, 25V, X5R, ±10%, SMD 0402; Manufacturer: SANYEAR; Manufacturer Part Number: C0402X5R224K250NT
footprint CAP-0402 (0402 (1005M) Capacitor)
pins: 1, 2

## C0402X5R273K160NTB
designator C?  Capacitance: 27nF  (hidden comment: *)
Capacitor, Ceramic (MLCC), 27nF, ±10%, 16V, X5R, ±10%, SMD 0402; Manufacturer: EYANG(Shenzhen Eyang Tech Development); Manufacturer Part Number: C0402X5R273K160NTB
footprint CAP-0402 (0402 (1005M) Capacitor)
pins: 1, 2

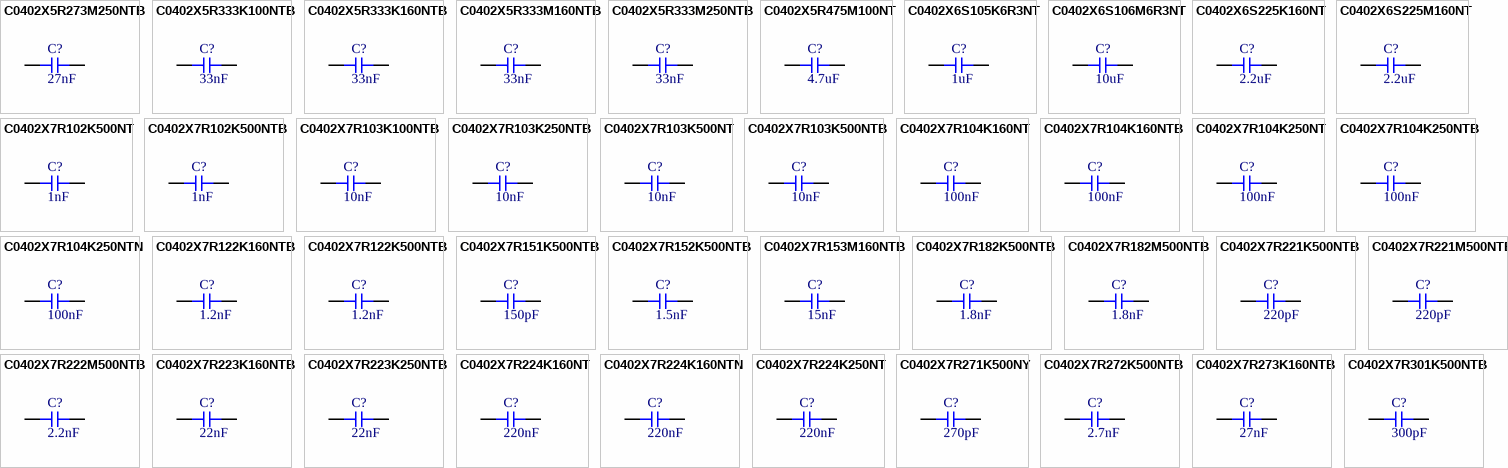
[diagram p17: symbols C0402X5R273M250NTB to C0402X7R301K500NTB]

## C0402X5R273M250NTB
designator C?  Capacitance: 27nF  (hidden comment: *)
Capacitor, Ceramic (MLCC), 27nF, ±20%, 25V, X5R, ±20%, SMD 0402; Manufacturer: EYANG(Shenzhen Eyang Tech Development); Manufacturer Part Number: C0402X5R273M250NTB
footprint CAP-0402 (0402 (1005M) Capacitor)
pins: 1, 2

## C0402X5R333K100NTB
designator C?  Capacitance: 33nF  (hidden comment: *)
Capacitor, Ceramic (MLCC), 33nF, ±10%, 10V, X5R, ±10%, SMD 0402; Manufacturer: EYANG(Shenzhen Eyang Tech Development); Manufacturer Part Number: C0402X5R333K100NTB
footprint CAP-0402 (0402 (1005M) Capacitor)
pins: 1, 2

## C0402X5R333K160NTB
designator C?  Capacitance: 33nF  (hidden comment: *)
Capacitor, Ceramic (MLCC), 33nF, ±10%, 16V, X5R, ±10%, SMD 0402; Manufacturer: EYANG(Shenzhen Eyang Tech Development); Manufacturer Part Number: C0402X5R333K160NTB
footprint CAP-0402 (0402 (1005M) Capacitor)
pins: 1, 2

## C0402X5R333M160NTB
designator C?  Capacitance: 33nF  (hidden comment: *)
Capacitor, Ceramic (MLCC), 33nF, ±20%, 16V, X5R, ±20%, SMD 0402; Manufacturer: EYANG(Shenzhen Eyang Tech Development); Manufacturer Part Number: C0402X5R333M160NTB
footprint CAP-0402 (0402 (1005M) Capacitor)
pins: 1, 2

## C0402X5R333M250NTB
designator C?  Capacitance: 33nF  (hidden comment: *)
Capacitor, Ceramic (MLCC), 33nF, ±20%, 25V, X5R, ±20%, SMD 0402; Manufacturer: EYANG(Shenzhen Eyang Tech Development); Manufacturer Part Number: C0402X5R333M250NTB
footprint CAP-0402 (0402 (1005M) Capacitor)
pins: 1, 2

## C0402X5R475M100NT
designator C?  Capacitance: 4.7uF  (hidden comment: *)
Capacitor, Ceramic (MLCC), 4.7uF, ±20%, 10V, X5R, ±20%, SMD 0402; Manufacturer: SANYEAR; Manufacturer Part Number: C0402X5R475M100NT
footprint CAP-0402 (0402 (1005M) Capacitor)
pins: 1, 2

## C0402X6S105K6R3NT
designator C?  Capacitance: 1uF  (hidden comment: *)
Capacitor, Ceramic (MLCC), 1uF, ±10%, 6.3V, ±10%, SMD 0402; Manufacturer: SANYEAR; Manufacturer Part Number: C0402X6S105K6R3NT
footprint CAP-0402 (0402 (1005M) Capacitor)
pins: 1, 2

## C0402X6S106M6R3NT
designator C?  Capacitance: 10uF  (hidden comment: *)
Capacitor, Ceramic (MLCC), 10uF, ±20%, 6.3V, ±20%, SMD 0402; Manufacturer: SANYEAR; Manufacturer Part Number: C0402X6S106M6R3NT
footprint CAP-0402 (0402 (1005M) Capacitor)
pins: 1, 2

## C0402X6S225K160NT
designator C?  Capacitance: 2.2uF  (hidden comment: *)
Capacitor, Ceramic (MLCC), 2.2uF, ±10%, 16V, ±10%, SMD 0402; Manufacturer: SANYEAR; Manufacturer Part Number: C0402X6S225K160NT
footprint CAP-0402 (0402 (1005M) Capacitor)
pins: 1, 2

## C0402X6S225M160NT
designator C?  Capacitance: 2.2uF  (hidden comment: *)
Capacitor, Ceramic (MLCC), 2.2uF, ±20%, 16V, ±20%, SMD 0402; Manufacturer: SANYEAR; Manufacturer Part Number: C0402X6S225M160NT
footprint CAP-0402 (0402 (1005M) Capacitor)
pins: 1, 2

## C0402X7R102K500NT
designator C?  Capacitance: 1nF  (hidden comment: *)
Capacitor, Ceramic (MLCC), 1nF, ±10%, 50V, X7R, ±10%, SMD 0402; Manufacturer: SANYEAR; Manufacturer Part Number: C0402X7R102K500NT
footprint CAP-0402 (0402 (1005M) Capacitor)
pins: 1, 2

## C0402X7R102K500NTB
designator C?  Capacitance: 1nF  (hidden comment: *)
Capacitor, Ceramic (MLCC), 1nF, ±10%, 50V, X7R, ±10%, SMD 0402; Manufacturer: EYANG(Shenzhen Eyang Tech Development); Manufacturer Part Number: C0402X7R102K500NTB
footprint CAP-0402 (0402 (1005M) Capacitor)
pins: 1, 2

## C0402X7R103K100NTB
designator C?  Capacitance: 10nF  (hidden comment: *)
Capacitor, Ceramic (MLCC), 10nF, ±10%, 10V, X7R, ±10%, SMD 0402; Manufacturer: EYANG(Shenzhen Eyang Tech Development); Manufacturer Part Number: C0402X7R103K100NTB
footprint CAP-0402 (0402 (1005M) Capacitor)
pins: 1, 2

## C0402X7R103K250NTB
designator C?  Capacitance: 10nF  (hidden comment: *)
Capacitor, Ceramic (MLCC), 10nF, ±10%, 25V, X7R, ±10%, SMD 0402; Manufacturer: EYANG(Shenzhen Eyang Tech Development); Manufacturer Part Number: C0402X7R103K250NTB
footprint CAP-0402 (0402 (1005M) Capacitor)
pins: 1, 2

## C0402X7R103K500NT
designator C?  Capacitance: 10nF  (hidden comment: *)
Capacitor, Ceramic (MLCC), 10nF, ±10%, 50V, X7R, ±10%, SMD 0402; Manufacturer: SANYEAR; Manufacturer Part Number: C0402X7R103K500NT
footprint CAP-0402 (0402 (1005M) Capacitor)
pins: 1, 2

## C0402X7R103K500NTB
designator C?  Capacitance: 10nF  (hidden comment: *)
Capacitor, Ceramic (MLCC), 10nF, ±10%, 50V, X7R, ±10%, SMD 0402; Manufacturer: EYANG(Shenzhen Eyang Tech Development); Manufacturer Part Number: C0402X7R103K500NTB
footprint CAP-0402 (0402 (1005M) Capacitor)
pins: 1, 2

## C0402X7R104K160NT
designator C?  Capacitance: 100nF  (hidden comment: *)
Capacitor, Ceramic (MLCC), 100nF, ±10%, 16V, X7R, ±10%, SMD 0402; Manufacturer: SANYEAR; Manufacturer Part Number: C0402X7R104K160NT
footprint CAP-0402 (0402 (1005M) Capacitor)
pins: 1, 2

## C0402X7R104K160NTB
designator C?  Capacitance: 100nF  (hidden comment: *)
Capacitor, Ceramic (MLCC), 100nF, ±10%, 16V, X7R, ±10%, SMD 0402; Manufacturer: EYANG(Shenzhen Eyang Tech Development); Manufacturer Part Number: C0402X7R104K160NTB
footprint CAP-0402 (0402 (1005M) Capacitor)
pins: 1, 2

## C0402X7R104K250NT
designator C?  Capacitance: 100nF  (hidden comment: *)
Capacitor, Ceramic (MLCC), 100nF, ±10%, 25V, X7R, ±10%, SMD 0402; Manufacturer: SANYEAR; Manufacturer Part Number: C0402X7R104K250NT
footprint CAP-0402 (0402 (1005M) Capacitor)
pins: 1, 2

## C0402X7R104K250NTB
designator C?  Capacitance: 100nF  (hidden comment: *)
Capacitor, Ceramic (MLCC), 100nF, ±10%, 25V, X7R, ±10%, SMD 0402; Manufacturer: EYANG(Shenzhen Eyang Tech Development); Manufacturer Part Number: C0402X7R104K250NTB
footprint CAP-0402 (0402 (1005M) Capacitor)
pins: 1, 2

## C0402X7R104K250NTN
designator C?  Capacitance: 100nF  (hidden comment: *)
Capacitor, Ceramic (MLCC), 100nF, ±10%, 25V, X7R, ±10%, SMD 0402; Manufacturer: EYANG(Shenzhen Eyang Tech Development); Manufacturer Part Number: C0402X7R104K250NTN
footprint CAP-0402 (0402 (1005M) Capacitor)
pins: 1, 2

## C0402X7R122K160NTB
designator C?  Capacitance: 1.2nF  (hidden comment: *)
Capacitor, Ceramic (MLCC), 1.2nF, ±10%, 16V, X7R, ±10%, SMD 0402; Manufacturer: EYANG(Shenzhen Eyang Tech Development); Manufacturer Part Number: C0402X7R122K160NTB
footprint CAP-0402 (0402 (1005M) Capacitor)
pins: 1, 2

## C0402X7R122K500NTB
designator C?  Capacitance: 1.2nF  (hidden comment: *)
Capacitor, Ceramic (MLCC), 1.2nF, ±10%, 50V, X7R, ±10%, SMD 0402; Manufacturer: EYANG(Shenzhen Eyang Tech Development); Manufacturer Part Number: C0402X7R122K500NTB
footprint CAP-0402 (0402 (1005M) Capacitor)
pins: 1, 2

## C0402X7R151K500NTB
designator C?  Capacitance: 150pF  (hidden comment: *)
Capacitor, Ceramic (MLCC), 150pF, ±10%, 50V, X7R, ±10%, SMD 0402; Manufacturer: EYANG(Shenzhen Eyang Tech Development); Manufacturer Part Number: C0402X7R151K500NTB
footprint CAP-0402 (0402 (1005M) Capacitor)
pins: 1, 2

## C0402X7R152K500NTB
designator C?  Capacitance: 1.5nF  (hidden comment: *)
Capacitor, Ceramic (MLCC), 1.5nF, ±10%, 50V, X7R, ±10%, SMD 0402; Manufacturer: EYANG(Shenzhen Eyang Tech Development); Manufacturer Part Number: C0402X7R152K500NTB
footprint CAP-0402 (0402 (1005M) Capacitor)
pins: 1, 2

## C0402X7R153M160NTB
designator C?  Capacitance: 15nF  (hidden comment: *)
Capacitor, Ceramic (MLCC), 15nF, ±20%, 16V, X7R, ±20%, SMD 0402; Manufacturer: EYANG(Shenzhen Eyang Tech Development); Manufacturer Part Number: C0402X7R153M160NTB
footprint CAP-0402 (0402 (1005M) Capacitor)
pins: 1, 2

## C0402X7R182K500NTB
designator C?  Capacitance: 1.8nF  (hidden comment: *)
Capacitor, Ceramic (MLCC), 1.8nF, ±10%, 50V, X7R, ±10%, SMD 0402; Manufacturer: EYANG(Shenzhen Eyang Tech Development); Manufacturer Part Number: C0402X7R182K500NTB
footprint CAP-0402 (0402 (1005M) Capacitor)
pins: 1, 2

## C0402X7R182M500NTB
designator C?  Capacitance: 1.8nF  (hidden comment: *)
Capacitor, Ceramic (MLCC), 1.8nF, ±20%, 50V, X7R, ±20%, SMD 0402; Manufacturer: EYANG(Shenzhen Eyang Tech Development); Manufacturer Part Number: C0402X7R182M500NTB
footprint CAP-0402 (0402 (1005M) Capacitor)
pins: 1, 2

## C0402X7R221K500NTB
designator C?  Capacitance: 220pF  (hidden comment: *)
Capacitor, Ceramic (MLCC), 220pF, ±10%, 50V, X7R, ±10%, SMD 0402; Manufacturer: EYANG(Shenzhen Eyang Tech Development); Manufacturer Part Number: C0402X7R221K500NTB
footprint CAP-0402 (0402 (1005M) Capacitor)
pins: 1, 2

## C0402X7R221M500NTB
designator C?  Capacitance: 220pF  (hidden comment: *)
Capacitor, Ceramic (MLCC), 220pF, ±20%, 50V, X7R, ±20%, SMD 0402; Manufacturer: EYANG(Shenzhen Eyang Tech Development); Manufacturer Part Number: C0402X7R221M500NTB
footprint CAP-0402 (0402 (1005M) Capacitor)
pins: 1, 2

## C0402X7R222M500NTB
designator C?  Capacitance: 2.2nF  (hidden comment: *)
Capacitor, Ceramic (MLCC), 2.2nF, ±20%, 50V, X7R, ±20%, SMD 0402; Manufacturer: EYANG(Shenzhen Eyang Tech Development); Manufacturer Part Number: C0402X7R222M500NTB
footprint CAP-0402 (0402 (1005M) Capacitor)
pins: 1, 2

## C0402X7R223K160NTB
designator C?  Capacitance: 22nF  (hidden comment: *)
Capacitor, Ceramic (MLCC), 22nF, ±10%, 16V, X7R, ±10%, SMD 0402; Manufacturer: EYANG(Shenzhen Eyang Tech Development); Manufacturer Part Number: C0402X7R223K160NTB
footprint CAP-0402 (0402 (1005M) Capacitor)
pins: 1, 2

## C0402X7R223K250NTB
designator C?  Capacitance: 22nF  (hidden comment: *)
Capacitor, Ceramic (MLCC), 22nF, ±10%, 25V, X7R, ±10%, SMD 0402; Manufacturer: EYANG(Shenzhen Eyang Tech Development); Manufacturer Part Number: C0402X7R223K250NTB
footprint CAP-0402 (0402 (1005M) Capacitor)
pins: 1, 2

## C0402X7R224K160NT
designator C?  Capacitance: 220nF  (hidden comment: *)
Capacitor, Ceramic (MLCC), 220nF, ±10%, 16V, X7R, ±10%, SMD 0402; Manufacturer: SANYEAR; Manufacturer Part Number: C0402X7R224K160NT
footprint CAP-0402 (0402 (1005M) Capacitor)
pins: 1, 2

## C0402X7R224K160NTN
designator C?  Capacitance: 220nF  (hidden comment: *)
Capacitor, Ceramic (MLCC), 220nF, ±10%, 16V, X7R, ±10%, SMD 0402; Manufacturer: EYANG(Shenzhen Eyang Tech Development); Manufacturer Part Number: C0402X7R224K160NTN
footprint CAP-0402 (0402 (1005M) Capacitor)
pins: 1, 2

## C0402X7R224K250NT
designator C?  Capacitance: 220nF  (hidden comment: *)
Capacitor, Ceramic (MLCC), 220nF, ±10%, 25V, X7R, ±10%, SMD 0402; Manufacturer: SANYEAR; Manufacturer Part Number: C0402X7R224K250NT
footprint CAP-0402 (0402 (1005M) Capacitor)
pins: 1, 2

## C0402X7R271K500NY
designator C?  Capacitance: 270pF  (hidden comment: *)
Capacitor, Ceramic (MLCC), 270pF, ±10%, 50V, X7R, ±10%, SMD 0402; Manufacturer: EYANG(Shenzhen Eyang Tech Development); Manufacturer Part Number: C0402X7R271K500NY
footprint CAP-0402 (0402 (1005M) Capacitor)
pins: 1, 2

## C0402X7R272K500NTB
designator C?  Capacitance: 2.7nF  (hidden comment: *)
Capacitor, Ceramic (MLCC), 2.7nF, ±10%, 50V, X7R, ±10%, SMD 0402; Manufacturer: EYANG(Shenzhen Eyang Tech Development); Manufacturer Part Number: C0402X7R272K500NTB
footprint CAP-0402 (0402 (1005M) Capacitor)
pins: 1, 2

## C0402X7R273K160NTB
designator C?  Capacitance: 27nF  (hidden comment: *)
Capacitor, Ceramic (MLCC), 27nF, ±10%, 16V, X7R, ±10%, SMD 0402; Manufacturer: EYANG(Shenzhen Eyang Tech Development); Manufacturer Part Number: C0402X7R273K160NTB
footprint CAP-0402 (0402 (1005M) Capacitor)
pins: 1, 2

## C0402X7R301K500NTB
designator C?  Capacitance: 300pF  (hidden comment: *)
Capacitor, Ceramic (MLCC), 300pF, ±10%, 50V, X7R, ±10%, SMD 0402; Manufacturer: EYANG(Shenzhen Eyang Tech Development); Manufacturer Part Number: C0402X7R301K500NTB
footprint CAP-0402 (0402 (1005M) Capacitor)
pins: 1, 2

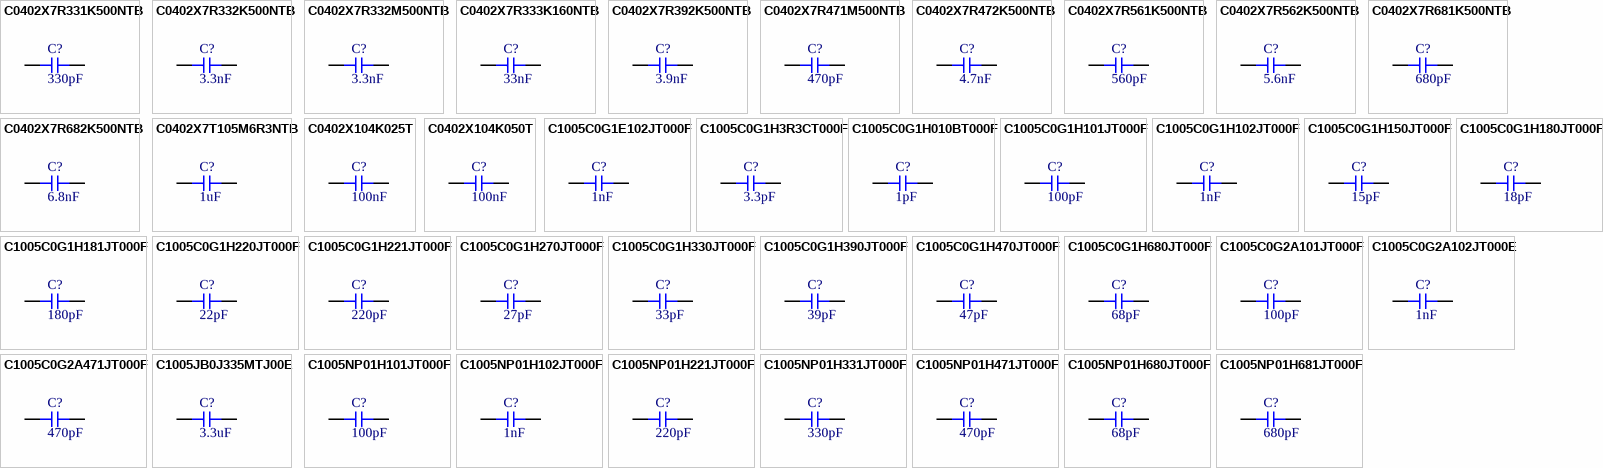
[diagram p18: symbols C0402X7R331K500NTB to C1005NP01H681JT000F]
